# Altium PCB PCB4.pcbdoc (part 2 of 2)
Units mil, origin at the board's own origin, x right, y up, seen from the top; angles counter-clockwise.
Board outline 2271.98 x 2855.49 mil, 2 copper layers (Top Layer, Bottom Layer); 93 components, 70 nets, 333 pads, 163 vias.
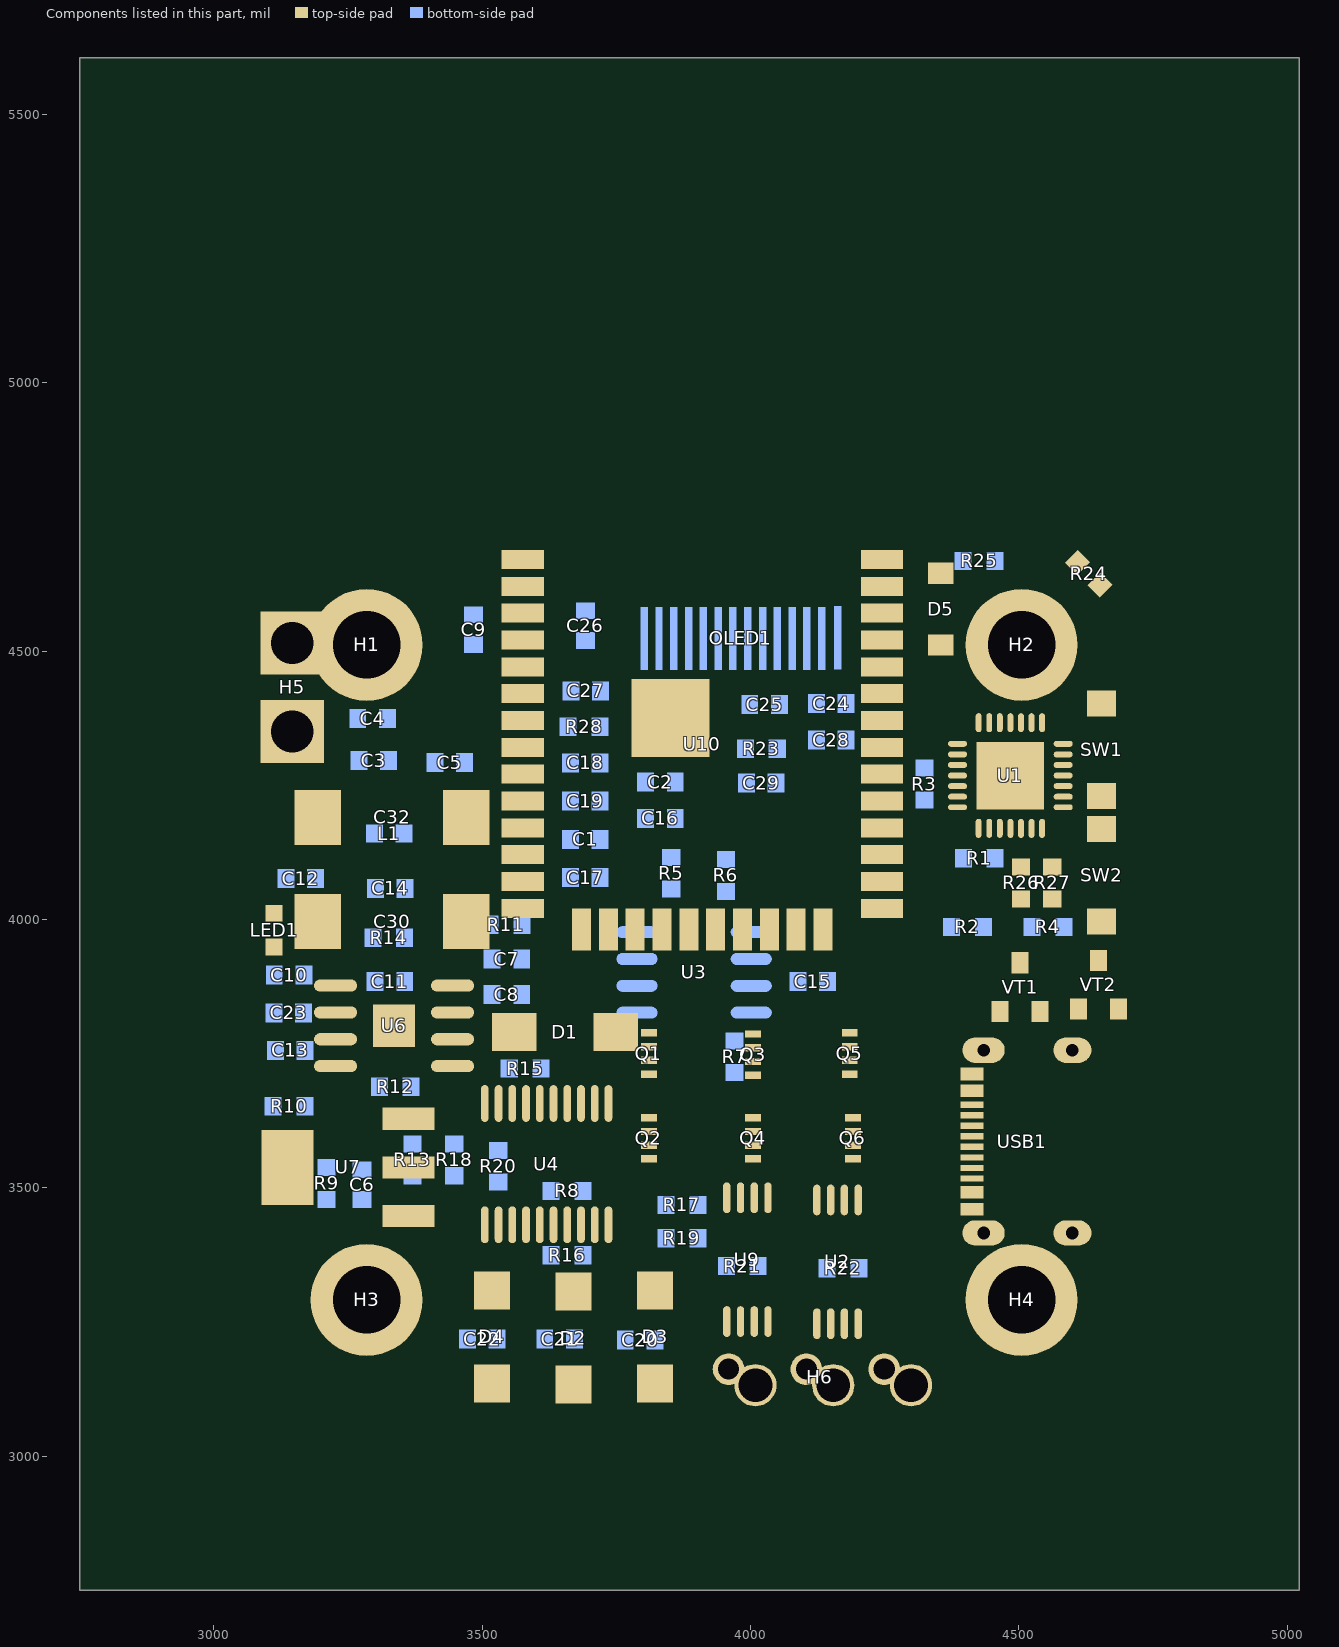
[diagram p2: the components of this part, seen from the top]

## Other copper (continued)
Bottom Layer:
  region net VDD_5V: 4053.48,3981.23 4028.47,3987.42 4028.47,3965.04 4053.48,3971.23
  region net 3V3: 4046.21,3936.07 4028.47,3937.42 4028.47,3915.04 4046.21,3916.39
  region net AS5600_SCL: 3833.66,3931.23 3815.47,3937.42 3815.47,3915.04 3833.66,3921.23
  region net AS5600_SDA: 3840.48,3881.23 3815.47,3887.42 3815.47,3865.04 3840.48,3871.23
  region net $1N3198: 3840.48,3831.23 3815.47,3837.42 3815.47,3815.04 3840.48,3821.23
  region net AS5600_SCL: 3847,4025.46 3857,4025.46 3869.01,4040.46 3834.99,4040.46
  region net AS5600_SCL: 3884.01,4061.34 3869.01,4072.22 3869.01,4040.46 3884.01,4051.34
  region net VDD_5V: 3904.44,4127.47 3869.01,4131.54 3869.01,4099.78 3904.44,4103.85
  region net AS5600_SDA: 3949,4021.46 3959,4021.46 3971.01,4036.46 3936.99,4036.46
  region net AS5600_SDA: 3986.01,4047.34 3986.01,4057.34 3971.01,4068.22 3971.01,4036.46
  region net VDD_5V: 3901.56,4127.47 3901.56,4103.85 3936.99,4095.78 3936.99,4127.54
  region net $1N3198: 3950.59,3800.14 3942.39,3794.2 3952.99,3765.92 3978.87,3789.54
  region net $1N4734: 4609.54,4004.8 4602.46,4011.88 4575.92,4003.01 4599.54,3977.13
  region net $1N4826: 4460.66,4081.99 4471.54,4096.99 4439.78,4096.99 4450.66,4081.99
  region net RTS: 4355.54,4007.54 4348.46,4000.46 4358.46,3972.79 4377.74,4003.01
  region net M0_GH1: 3633.34,3469.66 3644.22,3476.99 3612.46,3476.99 3623.34,3469.66
  region net $1N6924: 3718.54,3499 3703.54,3511.01 3703.54,3476.99 3718.54,3489
  region net VIN: 3676.25,4096.03 3680.19,4131.46 3648.69,4131.46 3652.63,4096.03
  region net VIN: 3676.25,4202.33 3652.63,4202.33 3648.69,4166.89 3680.19,4166.89
  region net AGND: 3731.37,4096.03 3735.31,4131.46 3703.81,4131.46 3707.75,4096.03
  region net AGND: 3731.37,4202.33 3707.75,4202.33 3703.81,4166.89 3735.31,4166.89
  region net VIN: 3871.37,4202.85 3875.31,4238.28 3843.81,4238.28 3847.75,4202.85
  region net AGND: 3816.25,4202.85 3820.19,4238.28 3788.69,4238.28 3792.63,4202.85
  region net VIN: 3279.81,4349.15 3256.19,4349.15 3254.69,4313.72 3286.19,4313.72
  region net VIN: 3279.81,4320.85 3283.75,4356.28 3252.25,4356.28 3256.19,4320.85
  region net $1N8822: 3271,3564.31 3258.5,3549.31 3293.5,3549.31 3281,3564.31
  region net $1N8755: 3578.66,3958.72 3568.66,3958.72 3557.81,3943.72 3589.31,3943.72
  region net $1N8699: 3523.44,3893.28 3534.19,3908.28 3502.69,3908.28 3513.44,3893.28
  region net $1N8699: 3523.44,3892.72 3513.44,3892.72 3502.69,3877.72 3534.19,3877.72
  region net $1N8699: 3506.77,3831.68 3534.19,3842.28 3502.69,3859.42 3492.63,3831.68
  region net $1N8426: 3186,3543 3186,3533 3192.99,3521.78 3192.99,3553.54
  region net $1N8426: 3115.34,3619.99 3126.22,3634.99 3094.46,3634.99 3105.34,3619.99
  region net $1N8755: 3578.66,3957.99 3589.54,3972.99 3557.78,3972.99 3568.66,3957.99
  region net $1N10899: 3379.84,3641.46 3383.54,3670.99 3351.78,3670.99 3360.16,3641.46
  region net $1N10899: 3379.84,3627.06 3360.16,3627.06 3352.99,3597.54 3387.01,3597.54
  region net VDD_5V: 3124.25,3842.85 3128.19,3878.28 3096.69,3878.28 3100.63,3842.85
  region net $1N10932: 3269.69,3871.68 3284.69,3866.28 3284.69,3894.18 3269.69,3881.68
  region net $1N10503: 3381.7,3901 3371.31,3901.72 3371.31,3878.5 3381.7,3891
  region net $1N10503: 3381.91,3864.72 3371.31,3893 3348.53,3866.28 3376.81,3855.68
  region net $1N10503: 3376,4155 3376,4165 3370.11,4177.01 3370.11,4142.99
  region net VDD_5V: 3248.08,4171.81 3248.08,4148.19 3283.51,4142.99 3283.51,4177.01
  region net VDD_5V: 3122.19,4118 3118.25,4093.72 3149.75,4093.72 3145.81,4118
  region net VDD_5V: 3124.25,3809.15 3100.63,3809.15 3098.69,3773.72 3130.19,3773.72
  region net 3V3: 4098.28,3861.56 4104.19,3866.28 4072.69,3866.28 4078.6,3861.56
  region net 3V3: 4063.76,3922.6 4051.81,3906.71 4072.69,3866.28 4072.69,3901.72
  region net $1N15151: 3279.68,3942.46 3303.89,3948.99 3280.27,3974.87 3272.61,3949.54
  region net 3V3: 3365.31,3990.53 3345.62,3990.53 3339.59,3983.01 3371.34,3983.01
  region net M0_GL1: 3607.8,3401.61 3601.86,3393.41 3612.46,3365.13 3636.08,3391.01
  region net $1N18188: 3718.54,3379 3703.54,3391.01 3703.54,3356.99 3718.54,3369
  region net $1N19387: 3932.54,3463 3932.54,3473 3917.54,3485.01 3917.54,3450.99
  region net VIN: 3871.37,4241.15 3847.75,4241.15 3843.81,4205.72 3875.31,4205.72
  region net AGND: 3779.76,4226.6 3767.81,4210.71 3788.69,4170.28 3788.69,4205.72
  region net AGND: 3816.25,4241.15 3792.63,4241.15 3788.69,4205.72 3820.19,4205.72
  region net VIN: 3676.25,4131.15 3652.63,4131.15 3648.69,4095.72 3680.19,4095.72
  region net AGND: 3731.37,4131.15 3707.75,4131.15 3703.81,4095.72 3735.31,4095.72
  region net M0_GH3: 3847.34,3382.34 3858.22,3388.99 3826.46,3388.99 3837.34,3382.34
  region net $1N20050: 3932.54,3411 3917.54,3423.01 3917.54,3388.99 3932.54,3401
  region net VIN: 3676.25,4238.39 3680.19,4273.82 3648.69,4273.82 3652.63,4238.39
  region net AGND: 3731.37,4238.39 3735.31,4273.82 3703.81,4273.82 3707.75,4238.39
  region net VIN: 3676.25,4167.21 3680.19,4202.64 3648.69,4202.64 3652.63,4167.21
  region net VIN: 3676.25,4273.51 3652.63,4273.51 3648.69,4238.07 3680.19,4238.07
  region net AGND: 3764.84,4230.2 3735.31,4238.07 3735.31,4202.64 3764.84,4210.51
  region net AGND: 3731.37,4273.51 3707.75,4273.51 3703.81,4238.07 3735.31,4238.07
  region net AGND: 3731.37,4167.21 3735.31,4202.64 3703.81,4202.64 3707.75,4167.21
  region net $1N25145: 3467.44,3250.72 3456.69,3235.72 3488.19,3235.72 3477.44,3250.72
  region net $1N24865: 3522.56,3250.72 3511.81,3235.72 3543.31,3235.72 3532.56,3250.72
  region net VDD_5V: 3124.25,3772.85 3127.75,3808.28 3096.25,3808.28 3100.63,3772.85
  region net VDD_5V: 3124.25,3879.15 3100.63,3879.15 3096.25,3843.72 3127.75,3843.72
  region net M0_OUT1_P: 3987.52,3332.59 3995.46,3326.39 4023.74,3336.99 3998.12,3360.87
  region net M0_OUT2_P: 4216.46,3371.88 4193.92,3367.01 4217.54,3341.13 4223.54,3364.8
  region net $1N42514: 4157,4450.6 4167,4450.6 4169.09,4465.6 4155.31,4465.6
  region net $1N43028: 4137.44,4449.3 4139.39,4464.3 4125.61,4464.3 4127.44,4449.3
  region net $1N43106: 4109,4449.3 4111.79,4464.3 4098.01,4464.3 4099,4449.3
  region net $1N42661: 4081,4458 4084.29,4464.3 4070.51,4464.3 4071,4458
  region net 3V3: 3973,4597.4 3963,4597.4 3960.21,4582.4 3973.99,4582.4
  region net OLED_RES: 3945,4449.3 3946.49,4464.3 3932.71,4464.3 3935,4449.3
  region net OLED_SCL: 3917,4449.3 3918.89,4464.3 3905.11,4464.3 3907,4449.3
  region net OLED_SDA: 3891.31,4449.3 3891.39,4464.3 3877.61,4464.3 3881.31,4449.3
  region net $1N44189: 3861,4449.3 3863.79,4464.3 3850.01,4464.3 3851,4449.3
  region net $1N43261: 3833,4449.3 3836.19,4464.3 3822.41,4464.3 3823,4449.3
  region net $1N43184: 3784.3,4546.63 3794.91,4464.3 3808.69,4554.06 3784.3,4560.77
  region net $1N43028: 4137.44,4434.72 4127.44,4434.72 4114.94,4419.72 4138.19,4419.72
  region net $1N43106: 4079.91,4416.84 4077.25,4428.32 4048.97,4417.72 4069.31,4388.56
  region net $1N42661: 4019.39,4428.32 4005.25,4428.32 3982.69,4417.72 4014.19,4405.44
  region net $1N43184: 3724.72,4570.12 3724.72,4580.12 3709.72,4590.87 3709.72,4559.37
  region net $1N43261: 3750.92,4421 3750.92,4431 3735.92,4443.5 3735.92,4408.5
  region net $1N44189: 3750.34,4353.77 3750.34,4363.77 3735.34,4375.78 3735.34,4341.76
  region net OLED_RES: 3987.44,4286.72 3976.69,4271.72 4008.19,4271.72 3997.44,4286.72
  region net OLED_RES: 3987.44,4285.99 3997.44,4285.99 4006.22,4300.99 3974.94,4300.99
  region net OLED_RES: 3963.86,4337.41 3974.46,4309.13 3998.08,4335.01 3969.8,4345.61
  region net ESP32_EN: 4416.54,4640.39 4422.48,4648.59 4411.88,4676.87 4388.26,4650.99
  region net ESP32_EN: 4369.52,4687.41 4380.12,4659.13 4403.74,4685.01 4375.46,4695.61
  region net ESP32_EN: 4416.54,4695.61 4388.26,4685.01 4411.88,4659.13 4422.48,4687.41
  region net $1N60145: 4486.2,4673 4471.2,4685.01 4471.2,4650.99 4486.2,4663
  region net M0_OUT3: 4330.43,3155.72 4307,3180 4297,3180 4271.54,3160.22
  region net M0_OUT3: 4273.02,3179.18 4257,3211.64 4247,3212.66 4228.95,3183.68
  region net ESP32_EN: 4608.75,4675.98 4597.1,4681.97 4590.03,4674.9 4596.02,4663.25
  region net ESP32_EN: 3583.94,4558.99 3596.41,4563 3596.41,4573 3583.94,4577.01
  region net $1N60145: 4663.01,4411.94 4659,4424.41 4649,4424.41 4644.99,4411.94
  region net ESP32_EN: 4519.94,3912.99 4532.41,3917 4532.41,3927 4519.94,3931.01
  region net OLED_SDA: 4232.62,4173.83 4221.01,4169 4226.78,4159 4241.62,4158.23
  region net OLED_SCL: 4174.06,4197.01 4161.59,4193 4161.59,4183 4174.06,4178.99
  region net OLED_RES: 3982.86,4308.6 3987.44,4296.75 3997.44,4298.53 4000.6,4311.75
  region net OLED_RES: 3991.09,4329.98 3979.44,4335.97 3972.37,4328.9 3978.36,4317.25
  region net OLED_RES: 4125.94,4272.99 4138.41,4277 4138.41,4287 4125.94,4291.01
  region net OLED_RES: 4338.02,4508.75 4332.03,4497.1 4339.1,4490.03 4350.75,4496.02
  region net AS5600_SCL: 4136.02,4116.75 4130.03,4105.1 4137.1,4098.03 4148.75,4104.02
  region net AS5600_SDA: 4112.14,4061.87 4099.7,4057.34 4107.98,4047.34 4123.63,4048
  region net $1N15151: 3123.94,3936.99 3136.41,3941 3136.41,3951 3123.94,3955.01
  region net RTS: 4372.75,3995.98 4361.1,4001.97 4354.03,3994.9 4360.02,3983.25
  region net $1N5701: 4443.88,3981.06 4437.2,3988.2 4430.12,3981.13 4426.03,3978.69
  region net $1N4734: 4596.99,4162.06 4601,4149.59 4611,4149.59 4615.01,4162.06
  region net RTS: 4352.02,4386.75 4348.46,4377.54 4355.54,4370.46 4364.75,4374.02
  region net $1N4826: 4477.98,3827.25 4483.97,3838.9 4476.9,3845.97 4465.25,3839.98
  region net USB-PWR-DP: 4414.02,4068.75 4408.03,4057.1 4415.1,4050.03 4426.75,4056.02
  region net USB-PWR-DP: 4454.06,3627.01 4441.59,3623 4441.59,3613 4454.06,3608.99
  region net USB-PWR-DM: 4449.25,4030.02 4460.9,4024.03 4467.97,4031.1 4461.98,4042.75
  region net USB-PWR-DM: 4491.77,3562.38 4491,3577.22 4481,3582.99 4476.17,3571.38
  region net M0_OUT2_P: 4211.85,3348.08 4218.44,3359.71 4212.06,3367.48 4200.42,3362
  region net M0_OUT1_P: 4004.02,3354.75 3998.03,3343.1 4005.1,3336.03 4016.75,3342.02
  region net $1N25145: 3521.43,3421.88 3525.43,3409.41 3535.43,3409.41 3539.44,3421.88
  region net $1N24865: 3518,3294.16 3522.56,3281.8 3532.56,3289.9 3532,3305.5
  region net M0_GL1: 3511.94,3452.99 3524.41,3457 3524.41,3467 3511.94,3471.01
  region net $1N18188: 3800.02,3550.75 3794.03,3539.1 3801.1,3532.03 3812.75,3538.02
  region net M0_GH3: 3547.02,3387.39 3551.02,3374.91 3561.02,3374.91 3565.03,3387.39
  region net M0_GH1: 3699.65,3437.73 3687.98,3433 3690.54,3423 3704.1,3420.28
  region net $1N6924: 3801.61,3699.77 3805.62,3687.3 3815.62,3687.3 3819.63,3699.77
  region net $1N8699: 3456.69,3775.93 3462.68,3787.58 3455.6,3794.66 3443.95,3788.67
  region net $1N8699: 3456.69,3775.93 3462.68,3787.58 3455.6,3794.66 3443.95,3788.67
  region net $1N8699: 3456.69,3775.93 3462.68,3787.58 3455.6,3794.66 3443.95,3788.67
  region net $1N10503: 3550.18,3797.56 3538.3,3793 3539.99,3783 3553.18,3779.8
  region net $1N10503: 3367.54,3883.25 3371.1,3892.46 3364.02,3899.54 3354.81,3895.98
  region net $1N10503: 3354.81,3872.02 3366.46,3866.03 3373.53,3873.1 3367.54,3884.75
  region net $1N8822: 3217.23,3719.25 3221,3706.55 3231,3706 3235.22,3718.26
  region net $1N8426: 3101.33,3644.06 3105.34,3631.59 3115.34,3631.59 3119.35,3644.06
  region net $1N10932: 3234.61,3867.68 3247.08,3871.68 3247.08,3881.68 3234.61,3885.69
  region net $1N20050: 4172.02,3704.75 4166.03,3693.1 4173.1,3686.03 4184.75,3692.02
  region net $1N19387: 4008.09,3692.18 4018.46,3688.46 4025.05,3696.02 4017.47,3707.55
  region net M0_IN3: 3750.02,4050.75 3748.46,4043.54 3755.54,4036.46 3762.75,4038.02
  region net M0_OUT2_CS: 3771.25,4074.02 3782.9,4068.03 3789.97,4075.1 3783.98,4086.75
  region net M0_OUT1_CS: 3802.99,4098.06 3807,4085.59 3817,4085.59 3821.01,4098.06
  region net M0_IN1: 3665.33,3566.44 3677.21,3571 3675.52,3581 3662.33,3584.2
  region net M0_IN1: 3714.06,3585.01 3701.59,3581 3701.59,3571 3714.06,3566.99
  region net M0_IN2: 3641.94,3596.99 3654.41,3601 3654.41,3611 3641.94,3615.01
  region net M0_IN2: 3700.06,3615.01 3687.59,3611 3687.59,3601 3700.06,3596.99
  region net M0_IN3: 3693.01,3721.94 3689,3734.41 3679,3734.41 3674.99,3721.94
  region net M0_OUT1_P: 3917.01,3635.94 3913,3648.41 3903,3648.41 3898.99,3635.94
  region net M0_OUT1_P: 3818.56,3753.88 3831.03,3757.89 3831.03,3767.89 3818.56,3771.9
  region net M0_OUT2_P: 4009.87,3748.91 4021.52,3742.92 4028.59,3749.99 4022.6,3761.64
  region net M0_OUT3: 4192.56,3753.88 4205.03,3757.89 4205.03,3767.89 4192.56,3771.9
  region net M0_OUT2_CS: 3777.55,3694.13 3765.74,3699.33 3763.82,3687.1 3774.76,3676.34
  region net M0_OUT1_CS: 3766.75,3737.98 3755.1,3743.97 3748.03,3736.9 3754.02,3725.25
  region net M0_OUT1_CS: 3941.86,3511.94 3937.85,3524.41 3927.85,3524.41 3923.84,3511.94
  region net M0_OUT1_CS: 3781.94,3594.99 3794.41,3599 3794.41,3609 3781.94,3613.01
  region net M0_OUT2_P: 4075.01,3599.94 4071,3612.41 4061,3612.41 4056.99,3599.94
  region net M0_OUT3: 4261.01,3599.94 4257,3612.41 4247,3612.41 4242.99,3599.94
  region net M0_OUT3: 4242.99,3584.06 4247,3571.59 4257,3571.59 4261.01,3584.06
  region net M0_OUT1_P: 3860.99,3554.06 3865,3541.59 3875,3541.59 3879.01,3554.06
  region net VDD_5V: 4176.75,3941.98 4165.1,3947.97 4158.03,3940.9 4164.02,3929.25
  region net 3V3: 3958.44,4618.67 3963,4606.79 3973,4608.48 3976.2,4621.67
  region net 3V3: 4042.99,4612.06 4047,4599.59 4057,4599.59 4061.01,4612.06
Inner1 (plane layer: these items are gaps in the copper):
  lines w10 net "": 3146,3438 3146,4258 ; 3263.27,4071.27 3264,4072 ; 3724.22,4330 3725.46,4331.24 3800.76,4331.24 3930,4202 3930,3826 4321.71,3826.23 ; 3742,4330 3584.66,4330 3448,4193.34 3448,3920 3262,3922 3262,4096 3364,4096 3364,4228 3480,4344 3416,4410 3416,4742 3000,4742 3000,4258 ; 4328,3674 3332.29,3674 ; 3000,4258 3146,4258 ; 3000,4258 3146,4258 ; 3000,4258 3004,3152 3006,3002 3882,3000 3882,3182 3873.72,3190.28 3543.14,3190.28 3543.14,3523.14 3543.08,3523.08 3303.72,3523.08 3303.72,3546.05 3315.67,3558 3578,3558 4320,3556 4320,3422 4642,3422 4644,4230 4547.88,4229.98 4426,4108.1 4426,3922 4214,3922 3984,4154 3934,4154 3930,4150 3928,3826 4328,3826 4327.29,3675.15 4326.14,3674 3332.29,3674 ; 3146,4258 3146,3424 3236,3424 ; 3236,3424 3236,3577.71 ; 3236,3424 3236,3577.71 ; 3236,3577.71 3332.29,3674 ; 3236,3577.71 3332.29,3674
Inner2 (plane layer: these items are gaps in the copper):
  lines w10 net "": 3755.48,4164 3756,4164 ; 3556.02,3658.17 3642.2,3572 4208,3572 4221.71,3585.71 4221.71,3648 4195.71,3674 3952.33,3674 3912.33,3714 3848,3714 3735,3827 3735,3981.32 3792,3982 3790,4164 3828,4164 3828,4220.19 3794.41,4253.78 3697.87,4253.78 3664.44,4220.36 3664.44,3968.39 3556.02,3859.97 3556.02,3658.17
